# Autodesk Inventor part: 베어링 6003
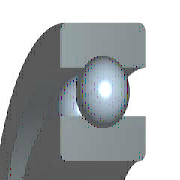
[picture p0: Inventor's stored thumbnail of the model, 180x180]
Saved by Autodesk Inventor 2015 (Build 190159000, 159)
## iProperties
Created: 2012-02
Part Number: 베어링 6003
Material: 강철, 연강
Description: 깊은 그루브 볼 베어링
Document SubType Name: Modeling
Standard: KS B 2023
Designer: mduedu
Standards Organization: KS
Language: ko-KR
Size Designation: 6003 - 17 x 35 x 10
Categories: <MemberInstance><Categories><Category DisplayName="샤프트 부품" InternalName="7f7aeb1f-a693-4053-b835-cee3144e0d98" Mnemonic="SHFT"><Category DisplayName="베어링" Inter
Density: 1 g/cm^3
Appearance: 주황색
IsCustomPart: 1
Author: mduedu
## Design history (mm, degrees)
sketch "스케치" dims "d0" = 4.68 (= -0.26 x WD + 0.26 x BD)
  geometry: L1 (2.66, 13)-(7.34, 13); L2 (5, 13)-(5, 10.66); L3 (5, 13)-(5, 15.34); L4 (3.261, 11.434)-(0, 11.434); L5 (0, 8.5)-(10, 8.5); L6 (3.261, 14.566)-(0, 14.566); L7 (0, 17.5)-(10, 17.5); L8 (10, 8.5)-(10, 11.434); L9 (6.739, 11.434)-(10, 11.434); L10 (6.739, 14.566)-(10, 14.566); L11 (10, 17.5)-(10, 14.566); L12 (-1.4, 0)-(8.4, 0) reference; L13 (0, -0.3)-(0, 5.3) reference
  constraints: 22 end point, 4 point on line, 2 collinear, 2 perpendicular, 2 symmetric about line, 1 midpoint, 1 parallel, 14 other
  dimensions: "d9" = 17 diameter of L5 L12 (= WD); "d11" = 35 diameter of L7 L12 (= BD); "d12" = 10 distance between parallel lines of L8 L13 (= KB); "d13" = 22.868 diameter of L9 L12 (= 0.326 x BD + 0.674 x WD)
revolve "본체" stored, may be unused: angle "d6" = 90 deg
revolve "볼" stored, may be unused: angle "d7" = 90 deg
pattern_circular "IDS_ARRAYBALL[SIMPL:T]" dims angle "d3" = 360 deg
body "Solid1"
fillet "모깎기1" dims "d1" = 0.3 (= KRS)
other parameters: "WD" = 17 [user parameter; used in 5 equation terms], "BD" = 35 [user parameter; used in 5 equation terms], "KB" = 10 [user parameter; used in 1 equation term], "KRS" = 0.3 [user parameter; used in 1 equation term], "d4" = 0, "d5" = 0, "d8" = 0, "d14" = 0, "d15" = 0, "BBA" = 0 [user parameter], "BC0" = 3250000 [user parameter], "BC" = 6050000 [user parameter], "BR" = 17.5 (= 0.5 x BD) [user parameter], "WR" = 8.5 (= 0.5 x WD) [user parameter]
